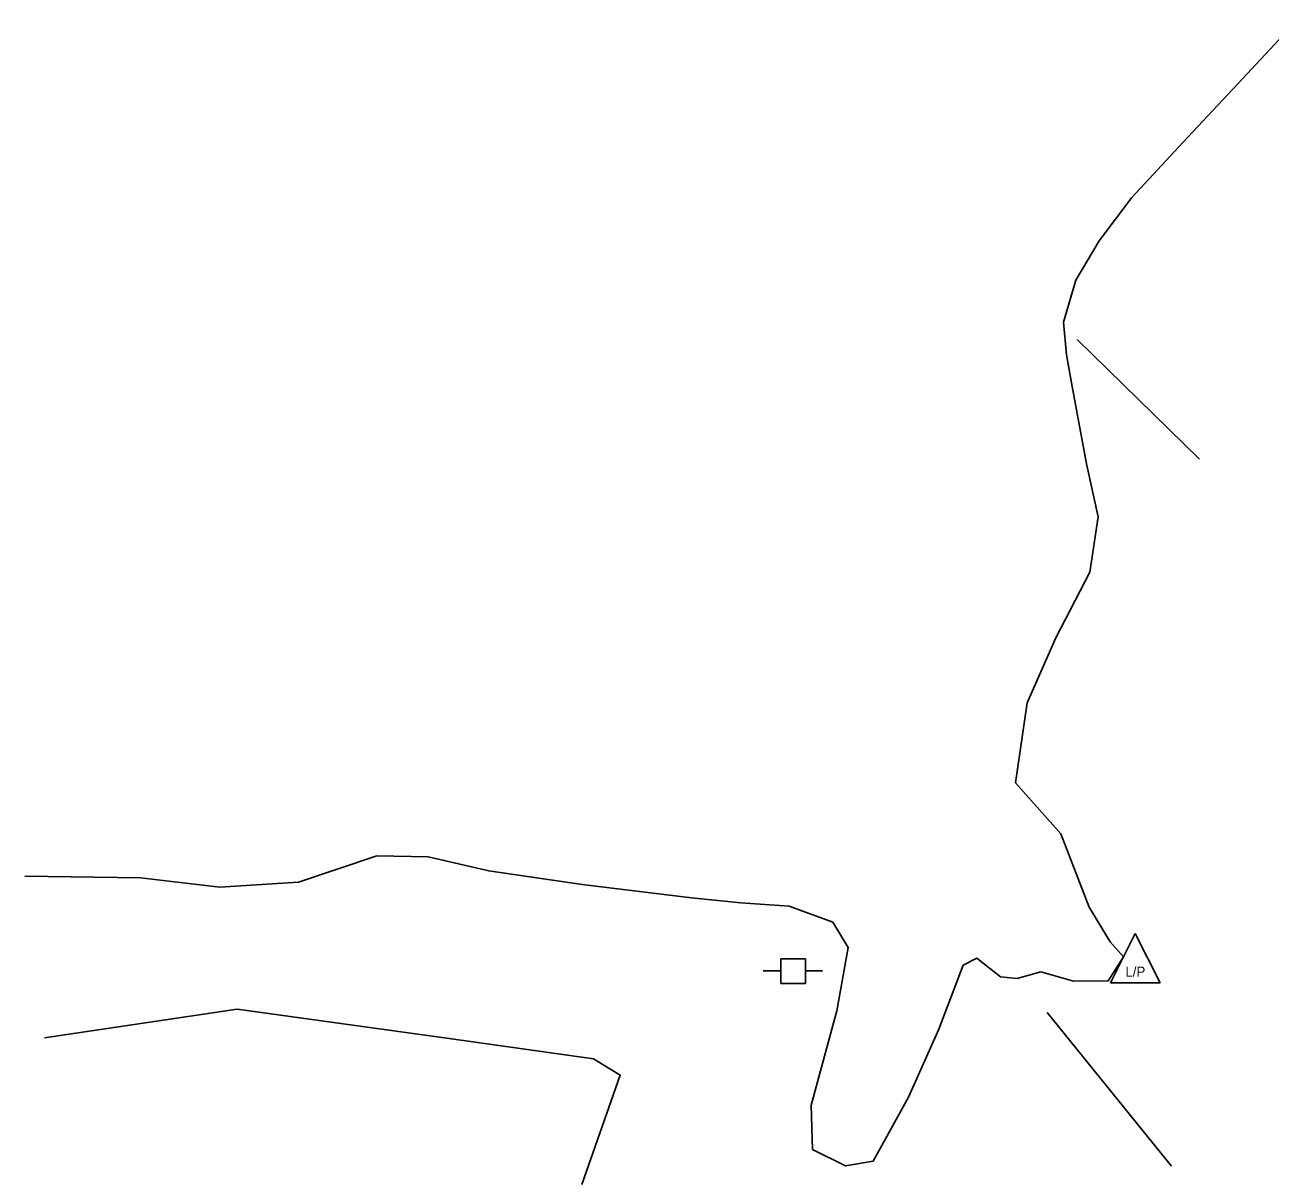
# Model space of a CAD drawing. Extents: x 2161152 to 2175754, y 602179 to 617749.
# Drawn here: x 2161409.6 to 2161661.1, y 603341.1 to 603573.6 of the extents above; entities that cross this region are included whole.
import ezdxf

# ---------------------------------------------------------------- set-up
doc = ezdxf.new("R2010")
doc.units = 0
for name, color, linetype in [('RD_EX_BldgApp_Sign', 7, 'Continuous'), ('RD_EX_UT', 7, 'Continuous'), ('RD_EX_VEG', 7, 'Continuous')]:
    doc.layers.add(name, color=color, linetype=linetype)

msp = doc.modelspace()

# ---------------------------------------------------------------- linework, layer by layer
at = {"layer": 'RD_EX_BldgApp_Sign'}
for p, q in [((2161622.17, 603510.06), (2161646.85, 603485.91)), ((2161641.22, 603343.09), (2161616.07, 603374.12))]:
    msp.add_line(p, q, dxfattribs=at)
at = {"layer": 'RD_EX_UT'}
for p, q in [((2161628.9, 603380.08), (2161633.9, 603390.08)), ((2161633.9, 603390.08), (2161638.9, 603380.08)), ((2161567.27, 603384.96), (2161562.27, 603384.96)), ((2161562.27, 603384.96), (2161562.28, 603379.96)), ((2161567.28, 603379.96), (2161567.27, 603384.96)), ((2161562.35, 603382.52), (2161558.71, 603382.52)), ((2161570.71, 603382.53), (2161567.24, 603382.53)), ((2161562.28, 603379.96), (2161567.28, 603379.96)), ((2161628.9, 603380.08), (2161638.9, 603380.08))]:
    msp.add_line(p, q, dxfattribs=at)
at = {"layer": 'RD_EX_VEG'}
for points in [[(2161665.72, 603573.64), (2161655.54, 603562.72), (2161643.57, 603549.95), (2161633.19, 603538.75), (2161626.57, 603530.02), (2161621.87, 603522.08), (2161619.37, 603513.61), (2161620.01, 603507.01), (2161621.16, 603500.61), (2161624.06, 603484.93), (2161626.41, 603474.24), (2161624.69, 603463.07), (2161617.85, 603449.8), (2161612.07, 603436.68), (2161609.67, 603420.54), (2161618.87, 603410.19), (2161624.6, 603395.36), (2161628.83, 603388.38), (2161631.53, 603385.34), (2161628.43, 603380.52), (2161621.44, 603380.45), (2161614.8, 603382.3), (2161610.03, 603381.01), (2161606.64, 603381.33), (2161601.91, 603385.09), (2161599.13, 603383.66), (2161594.19, 603370.73), (2161588.12, 603357.02), (2161580.93, 603344.08), (2161575.37, 603343.13), (2161568.71, 603346.45), (2161568.43, 603355.41), (2161573.59, 603374.45), (2161575.91, 603387.26), (2161572.79, 603392.34), (2161563.96, 603395.62), (2161554.22, 603396.24), (2161544.27, 603397.27), (2161522.15, 603399.96), (2161503.31, 603402.7), (2161491.04, 603405.53), (2161480.71, 603405.75), (2161464.91, 603400.47), (2161448.99, 603399.4), (2161432.94, 603401.31), (2161409.62, 603401.63)], [(2161413.57, 603369.02), (2161452.51, 603374.76), (2161495.29, 603368.83), (2161524.47, 603364.76), (2161529.85, 603361.47), (2161522.09, 603339.39)]]:
    msp.add_lwpolyline(points, dxfattribs=at)

# ---------------------------------------------------------------- texts
at = {"layer": 'RD_EX_UT'}
msp.add_text('L/P', height=2, dxfattribs=at).set_placement((2161631.9, 603381.36))

doc.saveas('drawing.dxf')
